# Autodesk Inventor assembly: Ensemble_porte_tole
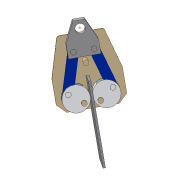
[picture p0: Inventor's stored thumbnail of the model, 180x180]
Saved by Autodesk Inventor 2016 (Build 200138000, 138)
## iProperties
Shininess: 64.0
Length Units: 11269
Angle Units: 11279
Time Units: 11290
Mass Units: 11283
Length Display Precision: 3
Angle Display Precision: 2
Compacted: True
Created: 2003-07
Part Number: Ensemble_porte_tole
Document SubType Name: Assembly
Designer: trameau
Density: 0.0
Volumn: 0.0
Area: 0.0
PropertySet Name: Model Information
Control State: 0
Master: False
Checked Out: False
Author: trameau
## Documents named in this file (6)
- G:\Consmec\1si\Cours\Leçon 05 - Statique\05-04-Statique avec frottement\06-02 Exercices statique Frottement\28-02 Exercices statique Frottement\28-02-02 Exercice stat frottement 2\06-02-02-2 Dessin 3d pincetole\Ensemble_porte_tole.iam
- G:\Consmec\1si\Cours\Leçon 05 - Statique\05-04-Statique avec frottement\06-02 Exercices statique Frottement\28-02 Exercices statique Frottement\28-02-02 Exercice stat frottement 2\06-02-02-2 Dessin 3d pincetole\Ensemble_flasque.iam
- G:\Consmec\1si\Cours\Leçon 05 - Statique\05-04-Statique avec frottement\06-02 Exercices statique Frottement\28-02 Exercices statique Frottement\28-02-02 Exercice stat frottement 2\06-02-02-2 Dessin 3d pincetole\Ensemble_étrier.iam
- G:\Consmec\1si\Cours\Leçon 05 - Statique\05-04-Statique avec frottement\06-02 Exercices statique Frottement\28-02 Exercices statique Frottement\28-02-02 Exercice stat frottement 2\06-02-02-2 Dessin 3d pincetole\Ensemble_molette.iam
- G:\Consmec\1si\Cours\Leçon 05 - Statique\05-04-Statique avec frottement\06-02 Exercices statique Frottement\28-02 Exercices statique Frottement\28-02-02 Exercice stat frottement 2\06-02-02-2 Dessin 3d pincetole\biellette.ipt
- G:\Consmec\1si\Cours\Leçon 05 - Statique\05-04-Statique avec frottement\06-02 Exercices statique Frottement\28-02 Exercices statique Frottement\28-02-02 Exercice stat frottement 2\06-02-02-2 Dessin 3d pincetole\tole.ipt
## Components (7 placed, 5 different names)
1. Ensemble_flasque:1 [sub-assembly] — Logement:1, Logement:2, Plaquer:2, Affleurer:1, Orientation:1, Plaquer:3
2. Ensemble_étrier:1 [sub-assembly] — Logement:5, Logement:6, Orientation:1
3. Ensemble_molette:1 [sub-assembly] — Logement:2, Logement:3, Tangente:1
4. Ensemble_molette:2 [sub-assembly] — Logement:1, Logement:4, Tangente:2
5. biellette:1 — Logement:3, Logement:6
6. biellette:2 — Logement:4, Logement:5
7. tole:1 — Plaquer:2, Affleurer:1, Plaquer:3, Tangente:1, Tangente:2
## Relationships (12: Insert 6, Mate 2, Tangent 2, Flush 1, Angle 1)
- Logement:1 [Insert]: Ensemble_flasque:1 ↔ Ensemble_molette:2
- Logement:2 [Insert]: Ensemble_flasque:1 ↔ Ensemble_molette:1
- Logement:3 [Insert]: Ensemble_molette:1 ↔ biellette:1
- Logement:4 [Insert]: Ensemble_molette:2 ↔ biellette:2
- Logement:5 [Insert]: Ensemble_étrier:1 ↔ biellette:2
- Logement:6 [Insert]: Ensemble_étrier:1 ↔ biellette:1
- Plaquer:2 [Mate]: Ensemble_flasque:1 ↔ tole:1
- Affleurer:1 [Flush]: Ensemble_flasque:1 ↔ tole:1
- Orientation:1 [Angle]: Ensemble_flasque:1 ↔ Ensemble_étrier:1
- Plaquer:3 [Mate]: Ensemble_flasque:1 ↔ tole:1
- Tangente:1: Ensemble_molette:1 ↔ tole:1
- Tangente:2: Ensemble_molette:2 ↔ tole:1
